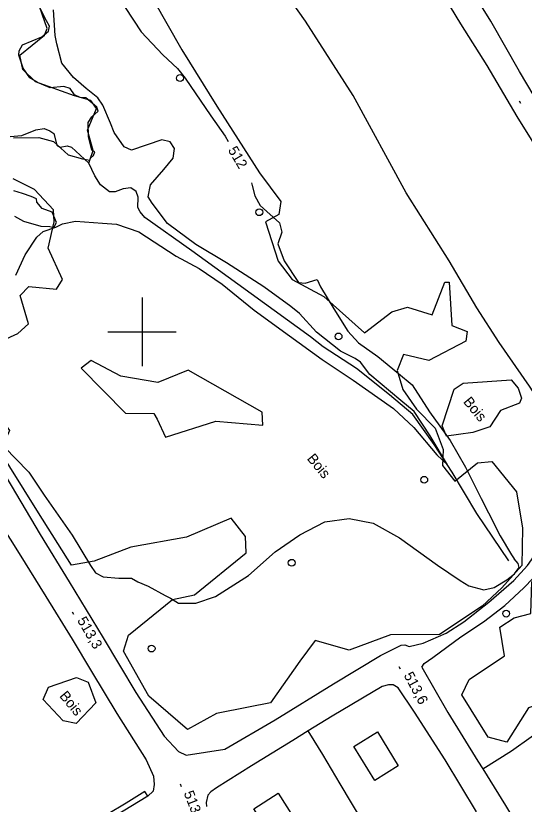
# Model space of a CAD drawing. Extents: x 347312 to 350503, y 6073086 to 6076432.
# Drawn here: x 348863.2 to 349011.5, y 6075462.2 to 6075692.2 of the extents above; entities that cross this region are included whole.
import ezdxf

# ---------------------------------------------------------------- set-up
doc = ezdxf.new("R2010")
doc.units = 0
for name, color, linetype in [('Level 1', 7, 'Continuous'), ('Level 19', 7, 'Continuous'), ('Level 2', 7, 'Continuous'), ('Level 21', 7, 'Continuous'), ('Level 22', 7, 'Continuous'), ('Level 3', 7, 'Continuous'), ('Level 31', 7, 'Continuous'), ('Level 36', 7, 'Continuous'), ('Level 4', 7, 'Continuous'), ('Level 44', 7, 'Continuous'), ('Level 61', 7, 'Continuous')]:
    doc.layers.add(name, color=color, linetype=linetype)

msp = doc.modelspace()

# ---------------------------------------------------------------- linework, layer by layer
at = {"layer": 'Level 1'}
for points in [[(348975.56, 6075579.95), (348966.43, 6075587.53), (348963.75, 6075591.11), (348962.24, 6075592.19), (348957.9, 6075594.39), (348950.9, 6075599.88), (348945.99, 6075605.3), (348943.46, 6075607.42), (348935.53, 6075613.12), (348924.7, 6075620.11), (348915.71, 6075625.45), (348907.41, 6075631.58), (348902.92, 6075637.5), (348901.78, 6075639.41), (348902.43, 6075642.88), (348906.35, 6075647.33), (348909.13, 6075650.7), (348909.47, 6075653.46), (348908.25, 6075655.46), (348905.79, 6075655.97), (348896.97, 6075652.95), (348894.84, 6075653.97), (348891.92, 6075658.1), (348890.85, 6075660.82), (348888.54, 6075666.12), (348887.13, 6075668.27), (348883.71, 6075671), (348879.97, 6075674.21), (348876.56, 6075678.38), (348875.14, 6075683.97), (348874.63, 6075686.48), (348874.13, 6075693.96)], [(348863.16, 6075616.48), (348865.94, 6075622.47), (348869.27, 6075627.63), (348871.15, 6075629.26), (348874.9, 6075630.57), (348876.84, 6075631.5), (348880.55, 6075632.31), (348888.49, 6075631.67), (348892.55, 6075631.42), (348899.11, 6075629.18), (348909.96, 6075622.07), (348916.68, 6075618.46), (348923.35, 6075613.91), (348932.76, 6075606.35), (348943.05, 6075598.84), (348952.6, 6075591.92), (348961.62, 6075585.84), (348973.37, 6075577.65), (348979.3, 6075572.1), (348986.07, 6075564.08), (348989.14, 6075561.16), (348984.07, 6075569.68), (348979.43, 6075576.76), (348975.56, 6075579.95)]]:
    msp.add_lwpolyline(points, dxfattribs=at)
at = {"layer": 'Level 19'}
msp.add_lwpolyline([(349003.26, 6075450.49), (348993.76, 6075444.88), (348982.81, 6075437.77), (348977.94, 6075434.93), (348973.18, 6075442.26), (348964.77, 6075456.49), (348957.78, 6075468.12), (348952.72, 6075476.71), (348950.22, 6075480.8), (348948.53, 6075483.56)], dxfattribs=at)
at = {"layer": 'Level 2'}
for points in [[(348879.44, 6075723.57), (348882.11, 6075718.08), (348884.5, 6075713.57), (348885.1, 6075711.55), (348884.31, 6075709.17), (348884.76, 6075707.82), (348887.01, 6075704.12), (348895.06, 6075694.62), (348899.8, 6075687.55), (348906.09, 6075680.84), (348910.32, 6075676.8), (348912.58, 6075674.04), (348920.05, 6075663.01), (348924.25, 6075657.09), (348925.18, 6075655.52)], [(348931.92, 6075643.49), (348932.13, 6075642.7), (348932.13, 6075642.7), (348932.91, 6075639.64), (348934.51, 6075636.83), (348936.45, 6075635.13), (348940.14, 6075631.8), (348940.83, 6075629.07), (348939.66, 6075625.69), (348941.46, 6075620.73), (348945.62, 6075614.4), (348947.58, 6075614.22), (348951.13, 6075615.21), (348952.13, 6075613.11), (348955.99, 6075606.68), (348960.08, 6075600.15), (348963.15, 6075596.75), (348968.8, 6075592.79), (348974.85, 6075587.8), (348978.84, 6075584.57), (348983.85, 6075576.68), (348989.91, 6075568.24), (348994.39, 6075560.53), (348998.95, 6075551.36), (349001.07, 6075547.13), (349004.47, 6075540.43), (349007.8, 6075534.96), (349008.6, 6075533.73)], [(348854.6, 6075578.62), (348859.24, 6075574.25), (348861.34, 6075571.22), (348860.33, 6075568.93), (348859.57, 6075567.63), (348860.21, 6075566.05), (348863.1, 6075563.01), (348866.99, 6075559.08), (348871.48, 6075552.33), (348879.61, 6075540.67), (348884.92, 6075531.83), (348886.44, 6075529.65)], [(348886.44, 6075529.65), (348888.64, 6075528.46), (348893.27, 6075528.16), (348896.93, 6075528.11), (348898.77, 6075527.08), (348901.78, 6075525.82), (348906.72, 6075523.07), (348908.34, 6075522.31), (348910.68, 6075520.86), (348915.74, 6075520.85), (348921.4, 6075522.75), (348931.12, 6075528.92), (348938.89, 6075535.81), (348946.1, 6075540.73), (348953.38, 6075544.58), (348960.48, 6075545.57), (348967.44, 6075544.2), (348975.13, 6075539.88), (348986.18, 6075531.89), (348992.82, 6075527.46), (348995.32, 6075525.92), (348999.79, 6075524.73), (349002.78, 6075525.4), (349006.49, 6075527.65), (349008.67, 6075529.38), (349010.08, 6075531.22), (349009.78, 6075532.4), (349008.6, 6075533.73)]]:
    msp.add_lwpolyline(points, dxfattribs=at)
at = {"layer": 'Level 21'}
for points in [[(349041, 6075611.4), (349035.56, 6075620.13), (349025.35, 6075636.76), (349017.87, 6075649.37), (349009.45, 6075662.84), (349000.71, 6075677.69), (348993.03, 6075689.81), (348985.01, 6075703.08), (348975.04, 6075719.14), (348967.46, 6075732.31), (348959.39, 6075746.72), (348955.27, 6075756.09), (348952.16, 6075765.42), (348948.43, 6075777.66), (348948.23, 6075778.6)], [(349018.73, 6075661.58), (349010.15, 6075675.97), (349001.8, 6075690.62), (348992.75, 6075705.2)], [(348795.88, 6075666.04), (348796.06, 6075662.21), (348797.02, 6075659.33), (348799.81, 6075654.82), (348805.45, 6075645.9), (348815.1, 6075630.18), (348825.15, 6075614.78), (348838.03, 6075593.86), (348846.54, 6075579.59), (348858.99, 6075559.88), (348870.32, 6075540.88), (348878.71, 6075527.02), (348888.64, 6075510.69), (348898.24, 6075494.76), (348906.45, 6075482.02), (348910.6, 6075477.5), (348912.89, 6075476.47), (348924.17, 6075478.22), (348938.88, 6075486.8), (348955.83, 6075497.3), (348969.56, 6075505.52), (348975.65, 6075508.61), (348976.73, 6075508.67), (348977.96, 6075508.19)], [(348977.96, 6075508.19), (348982.05, 6075509.17), (348988.74, 6075512.09), (348993.86, 6075515.35), (349001.19, 6075521.12), (349008.45, 6075527.43), (349012.53, 6075531.86), (349016.33, 6075537.34), (349020.7, 6075544.87), (349022.42, 6075548.77), (349024.14, 6075553.13), (349027.76, 6075560.18), (349030.81, 6075567.83), (349034.44, 6075577.3), (349038.61, 6075586.24), (349041.63, 6075594), (349041.78, 6075599.61), (349040.99, 6075606.61), (349041, 6075611.4)], [(348981.68, 6075502.11), (348982.36, 6075503.19), (348984.87, 6075504.97), (348993, 6075510.96), (348999.63, 6075515.4), (349005.84, 6075520.16), (349011.43, 6075525.31), (349016.72, 6075530.82), (349020.58, 6075536.05), (349023.85, 6075541.99), (349026.18, 6075545.8), (349028.38, 6075550.85), (349029.59, 6075553.74), (349030, 6075554.69), (349031.75, 6075558.75), (349036.54, 6075566.93), (349040.88, 6075574.21), (349042.84, 6075578.01), (349045.82, 6075584.39), (349047.48, 6075588.55), (349048.78, 6075594.21), (349050.03, 6075596.63)], [(348856.15, 6075547.84), (348864.2, 6075535.29), (348871.97, 6075522.73), (348879.59, 6075510.34), (348885.22, 6075500.88), (348892.65, 6075488.63), (348901.24, 6075475.16), (348903.35, 6075470.37), (348903.53, 6075467.89), (348903.23, 6075465.99), (348901.69, 6075464.54)], [(348981.68, 6075502.11), (348989.28, 6075488.94), (348998.03, 6075474.76), (348999.46, 6075472.47), (349006.1, 6075461.83), (349014.24, 6075448.19)], [(348997.58, 6075459.92), (348988.44, 6075475.13), (348979.55, 6075489.03), (348974.76, 6075496.11), (348973.24, 6075496.95), (348971.97, 6075497.03), (348970.03, 6075496.55), (348955.51, 6075487.83), (348948.53, 6075483.56), (348943.99, 6075480.77), (348931.93, 6075473.34), (348921.75, 6075466.94), (348920.04, 6075465.82), (348919.21, 6075464.83), (348918.72, 6075462.7), (348918.85, 6075461.46)], [(348901.69, 6075464.54), (348887.33, 6075455.72)]]:
    msp.add_lwpolyline(points, dxfattribs=at)
at = {"layer": 'Level 22'}
for points in [[(349027.76, 6075560.18), (349024.06, 6075566.6), (349021.08, 6075571.79), (349013.06, 6075584.09), (349004.19, 6075596.88), (348997.71, 6075606.99), (348989.58, 6075620.68), (348977.07, 6075640.52), (348961.66, 6075668.9), (348947.69, 6075690.67), (348939.62, 6075702.14), (348934.53, 6075707.68), (348924.5, 6075718.42), (348912.34, 6075729.35), (348905.37, 6075734.82), (348896.81, 6075740.19)], [(348999.46, 6075472.47), (349007.86, 6075477.77), (349019.32, 6075485.91), (349026.01, 6075490.55), (349033.93, 6075497.7), (349044.9, 6075508.44), (349052.74, 6075517.49), (349058.32, 6075525.27), (349069.03, 6075544.82), (349073.65, 6075557.64)], [(348901.69, 6075464.54), (348900.87, 6075465.84), (348895.33, 6075462.45), (348884.32, 6075455.81), (348874.88, 6075449.87), (348864.55, 6075443.73), (348853.03, 6075436.67), (348850.81, 6075435.72), (348850.11, 6075435.75), (348849.01, 6075436.26), (348848.15, 6075437.2), (348847.06, 6075438.41), (348840.37, 6075449.16), (348834.18, 6075459.65), (348826.97, 6075471.1), (348820.1, 6075482.15), (348819.03, 6075481.41)]]:
    msp.add_lwpolyline(points, dxfattribs=at)
at = {"layer": 'Level 3'}
for p, q in [((349010.06, 6075667.34), (349010.48, 6075666.66)), ((348879.58, 6075518.33), (348879.98, 6075517.63)), ((348974.97, 6075502.36), (348975.35, 6075501.66)), ((348911.1, 6075468.12), (348911.39, 6075467.37))]:
    msp.add_line(p, q, dxfattribs=at)
at = {"layer": 'Level 31'}
for points in [[(348967.92, 6075469.12), (348961.82, 6075479.05), (348968.68, 6075483.26), (348974.78, 6075473.34), (348967.92, 6075469.12)], [(348938.8, 6075451.08), (348932.6, 6075460.84), (348939.75, 6075465.38), (348945.95, 6075455.61), (348938.8, 6075451.08)]]:
    msp.add_lwpolyline(points, dxfattribs=at)
at = {"layer": 'Level 36'}
for centre in [(348911.11, 6075674.04), (348934.23, 6075634.89), (348957.34, 6075598.63), (348982.34, 6075556.81), (348943.68, 6075532.6), (349006.26, 6075517.77), (348902.79, 6075507.59)]:
    msp.add_circle(centre, 1, dxfattribs=at)
at = {"layer": 'Level 4'}
for points in [[(348884.48, 6075649.24), (348884.98, 6075650.63), (348885.84, 6075651.42), (348886.23, 6075652.49), (348885.33, 6075653.02), (348884.37, 6075656.97), (348884.3, 6075661.05), (348885.32, 6075662.72), (348887.2, 6075664.36), (348886.82, 6075665.54), (348883.61, 6075668.3), (348881.96, 6075668.37), (348880.26, 6075669.14), (348878.99, 6075671.02), (348877.15, 6075671.6), (348873.23, 6075671.13), (348869.54, 6075672.74), (348867.23, 6075674.06), (348865.31, 6075676.91), (348864.09, 6075680.71), (348864.12, 6075681.94), (348865.15, 6075683.7), (348870.77, 6075686.02), (348872.74, 6075687.73), (348872.96, 6075689.19), (348872.12, 6075690.75), (348869.12, 6075696.69)], [(348861.52, 6075657), (348864.97, 6075657.22), (348869, 6075658.9), (348871.43, 6075659.34), (348873.06, 6075658.66), (348874.3, 6075657.81), (348875.19, 6075654.48), (348876.12, 6075653.82), (348878.14, 6075654.21), (348879.39, 6075653.89), (348884.48, 6075649.24)], [(349007.08, 6075533.15), (348997.66, 6075546.96), (348990.49, 6075559.08), (348985.28, 6075567.12), (348979.03, 6075575.88), (348972.21, 6075581.6), (348962.6, 6075589.3), (348952.9, 6075595.65), (348949.12, 6075598.55), (348914.54, 6075623.57), (348900.84, 6075633.36), (348899.46, 6075635.01), (348898.79, 6075636.26), (348898.83, 6075639.3), (348898.28, 6075640.95), (348896.77, 6075642.04), (348894.47, 6075641.71), (348892.12, 6075640.82), (348890.51, 6075640.84), (348887.85, 6075642.85), (348886.28, 6075645.46), (348884.48, 6075649.24)], [(348862.75, 6075633.71), (348865.42, 6075632.23), (348870.48, 6075630.79), (348873.07, 6075630.67), (348874.28, 6075630.4), (348875.08, 6075631.89), (348873.75, 6075634.93), (348870.88, 6075636.01), (348869.31, 6075637.8), (348869.2, 6075638.75), (348867.66, 6075639.51), (348865.09, 6075640.32), (348862.57, 6075641.16)]]:
    msp.add_lwpolyline(points, dxfattribs=at)
at = {"layer": 'Level 44'}
for points in [[(348862.5, 6075656.63), (348869.85, 6075656.73), (348874.17, 6075655.56), (348878.45, 6075651.58), (348882.63, 6075650.44), (348884.74, 6075650.08), (348885.74, 6075652.87), (348884.07, 6075658.85), (348886.71, 6075665.11), (348885.03, 6075667.48), (348880.29, 6075668.81), (348868.96, 6075672.96), (348865.25, 6075676.5), (348864.32, 6075680.69), (348871.54, 6075686.53), (348872.3, 6075688.51), (348868.73, 6075698.94)], [(348903.24, 6075697.09), (348911.58, 6075682.24), (348921.83, 6075665.82), (348934.27, 6075646.41), (348940.5, 6075638.05), (348939.9, 6075634.25), (348936, 6075632.07), (348939.71, 6075620.57), (348943.83, 6075615.28), (348953.1, 6075610.33), (348964.88, 6075599.66), (348972.86, 6075605.82), (348977.43, 6075607.21), (348984.63, 6075604.91), (348988.4, 6075614.49), (348989.63, 6075614.46), (348990.36, 6075601.85), (348994.89, 6075600.04), (348994.47, 6075597.29), (348983.66, 6075591.63), (348976.32, 6075593.37), (348974.49, 6075588.7), (348976.12, 6075583.13), (348980.13, 6075577.43), (348985.55, 6075571.84), (348987.86, 6075565.64), (348987.68, 6075560.97), (348991.31, 6075556.45), (348997.9, 6075561.76), (349002.06, 6075562.2), (349009.32, 6075553.33), (349011.06, 6075542.75), (349010.8, 6075531.86), (349005, 6075525.25), (348999.3, 6075519.95)], [(348855.8, 6075595.89), (348863.81, 6075599.51), (348866.87, 6075602.35), (348864.42, 6075610.54), (348866.98, 6075613.26), (348875.06, 6075612.44), (348876.8, 6075615.24), (348872.62, 6075624.41), (348874.4, 6075632.05), (348874.16, 6075635.61), (348868.61, 6075641.48), (348862.43, 6075644.66)], [(348906.88, 6075569.24), (348921.56, 6075573.89), (348935.22, 6075572.72), (348935.07, 6075576.51), (348913.47, 6075588.83), (348904.57, 6075585.21), (348893.79, 6075587.09), (348885.15, 6075591.66), (348882.22, 6075589.38), (348895.17, 6075576.21), (348903.49, 6075576.19), (348904.41, 6075574.55), (348906.88, 6075569.24)], [(348999.3, 6075519.95), (348986.76, 6075511.67), (348972.5, 6075511.58), (348960.4, 6075507.12), (348950.54, 6075509.91), (348946.03, 6075503.92), (348937.5, 6075491.75), (348931.04, 6075490.46), (348921.73, 6075488.61), (348913.24, 6075483.97), (348901.96, 6075493.7), (348894.61, 6075506.84), (348896.03, 6075511.47), (348908.85, 6075521.94), (348915.31, 6075523.23), (348930.43, 6075535.46), (348930.22, 6075540.24), (348926.02, 6075545.63), (348913, 6075540.09), (348896.75, 6075537.15), (348886, 6075533.05), (348879.4, 6075531.93), (348869.77, 6075547.19), (348845.11, 6075586.68)], [(349010.17, 6075579.22), (349004.61, 6075577.03), (349001.46, 6075572.31), (348996.52, 6075570.63), (348992.35, 6075570.02), (348988.81, 6075569.57), (348987.6, 6075572.55), (348991.06, 6075583.23), (348993.73, 6075584.99), (349007.75, 6075586.01), (349009.75, 6075583.53), (349010.75, 6075580.61), (349010.17, 6075579.22)], [(349026.14, 6075494.86), (349012.78, 6075490.26), (349006.5, 6075480.25), (349001.04, 6075481.73), (348993.28, 6075494.1), (348995.43, 6075498.57), (349005.78, 6075505.5), (349004.37, 6075513.81), (349008.62, 6075516.56), (349013.43, 6075517.84), (349013.78, 6075527), (349016.58, 6075529.61), (349021.97, 6075529.12), (349026.36, 6075534.71), (349032.22, 6075539.26), (349034.66, 6075541.58), (349048.33, 6075518.17), (349047.38, 6075514.97), (349034.48, 6075504.18), (349026.14, 6075494.86)], [(348886.5, 6075491.78), (348880.83, 6075485.74), (348877.04, 6075486.5), (348871.11, 6075492.7), (348872.76, 6075496.33), (348880.84, 6075499.11), (348884.25, 6075497.73), (348886.5, 6075491.78)]]:
    msp.add_lwpolyline(points, dxfattribs=at)
at = {"layer": 'Level 61'}
for p, q in [((348900, 6075610), (348900, 6075590)), ((348890, 6075600), (348910, 6075600))]:
    msp.add_line(p, q, dxfattribs=at)

# ---------------------------------------------------------------- texts
at = {"layer": 'Level 2'}
msp.add_text('512', height=3, rotation=300.5187, dxfattribs=at).set_placement((348924.98, 6075653.02))
at = {"layer": 'Level 3'}
for s, rotation, p in [('513,3', 300.1267, (348880.99, 6075515.81)), ('513,6', 298.0174, (348976.29, 6075499.8)), ('513,4', 291.3704, (348912.12, 6075465.43))]:
    msp.add_text(s, height=3, rotation=rotation, dxfattribs=at).set_placement(p)
at = {"layer": 'Level 44'}
for p in [(348993.57, 6075579.51), (348947.98, 6075562.93), (348875.73, 6075493.68)]:
    msp.add_text('Bois', height=3, rotation=309.568, dxfattribs=at).set_placement(p)

doc.saveas('drawing.dxf')
